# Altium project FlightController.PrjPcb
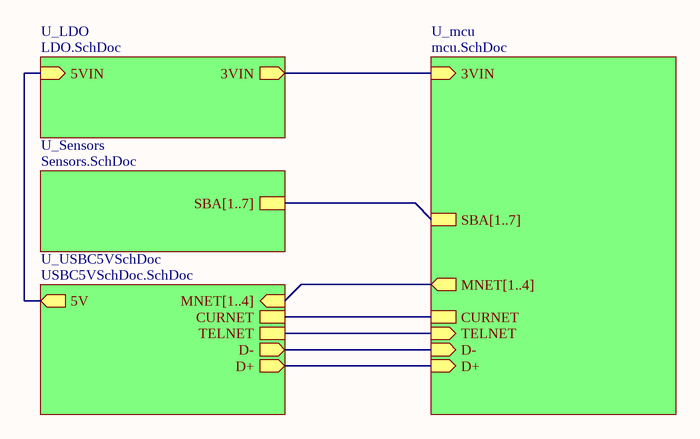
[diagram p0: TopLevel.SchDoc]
6 sheets, 64 parts. Net scope: hierarchical (ports join the sheet entries above them; power ports are global).
Board file: P2cbcopynext.PcbDoc
Sheets:
  TopLevel.SchDoc
    U_mcu = mcu.SchDoc
      U_VDDCap = VDDCap.SchDoc
      U_VDDCap = VDDCap.SchDoc
      U_VDDCap = VDDCap.SchDoc
      U_VDDCap = VDDCap.SchDoc
      U_VDDCap = VDDCap.SchDoc
    U_LDO = LDO.SchDoc
    U_Sensors = Sensors.SchDoc
      U_VDDCap = VDDCap.SchDoc
      U_VDDCap = VDDCap.SchDoc
      U_VDDCap = VDDCap.SchDoc
      U_VDDCap = VDDCap.SchDoc
    U_USBC5VSchDoc = USBC5VSchDoc.SchDoc

## Sheet TopLevel.SchDoc
size A; SheetNumber: 1; SheetTotal: 6

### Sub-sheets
U_LDO = LDO.SchDoc: 3VIN (out), 5VIN (in)
U_mcu = mcu.SchDoc: D- (in), D+ (in), TELNET (in), CURNET, 3VIN (in), SBA[1..7], MNET[1..4] (out)
U_Sensors = Sensors.SchDoc: SBA[1..7]
U_USBC5VSchDoc = USBC5VSchDoc.SchDoc: 5V (out), D+ (out), D- (out), MNET[1..4] (in), CURNET, TELNET

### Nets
3V3: sheet U_mcu/3VIN, sheet U_LDO/3VIN
5V_RAIL: sheet U_LDO/5VIN, sheet U_USBC5VSchDoc/5V
CURNET: sheet U_mcu/CURNET, sheet U_USBC5VSchDoc/CURNET
D+: sheet U_mcu/D+, sheet U_USBC5VSchDoc/D+
D-: sheet U_mcu/D-, sheet U_USBC5VSchDoc/D-
TELNET: sheet U_mcu/TELNET, sheet U_USBC5VSchDoc/TELNET

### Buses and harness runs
bus sheet U_mcu/MNET[1..4] = sheet U_USBC5VSchDoc/MNET[1..4]
bus sheet U_mcu/SBA[1..7] = sheet U_Sensors/SBA[1..7]

## Sheet mcu.SchDoc
size A; SheetNumber: 6; SheetTotal: 6
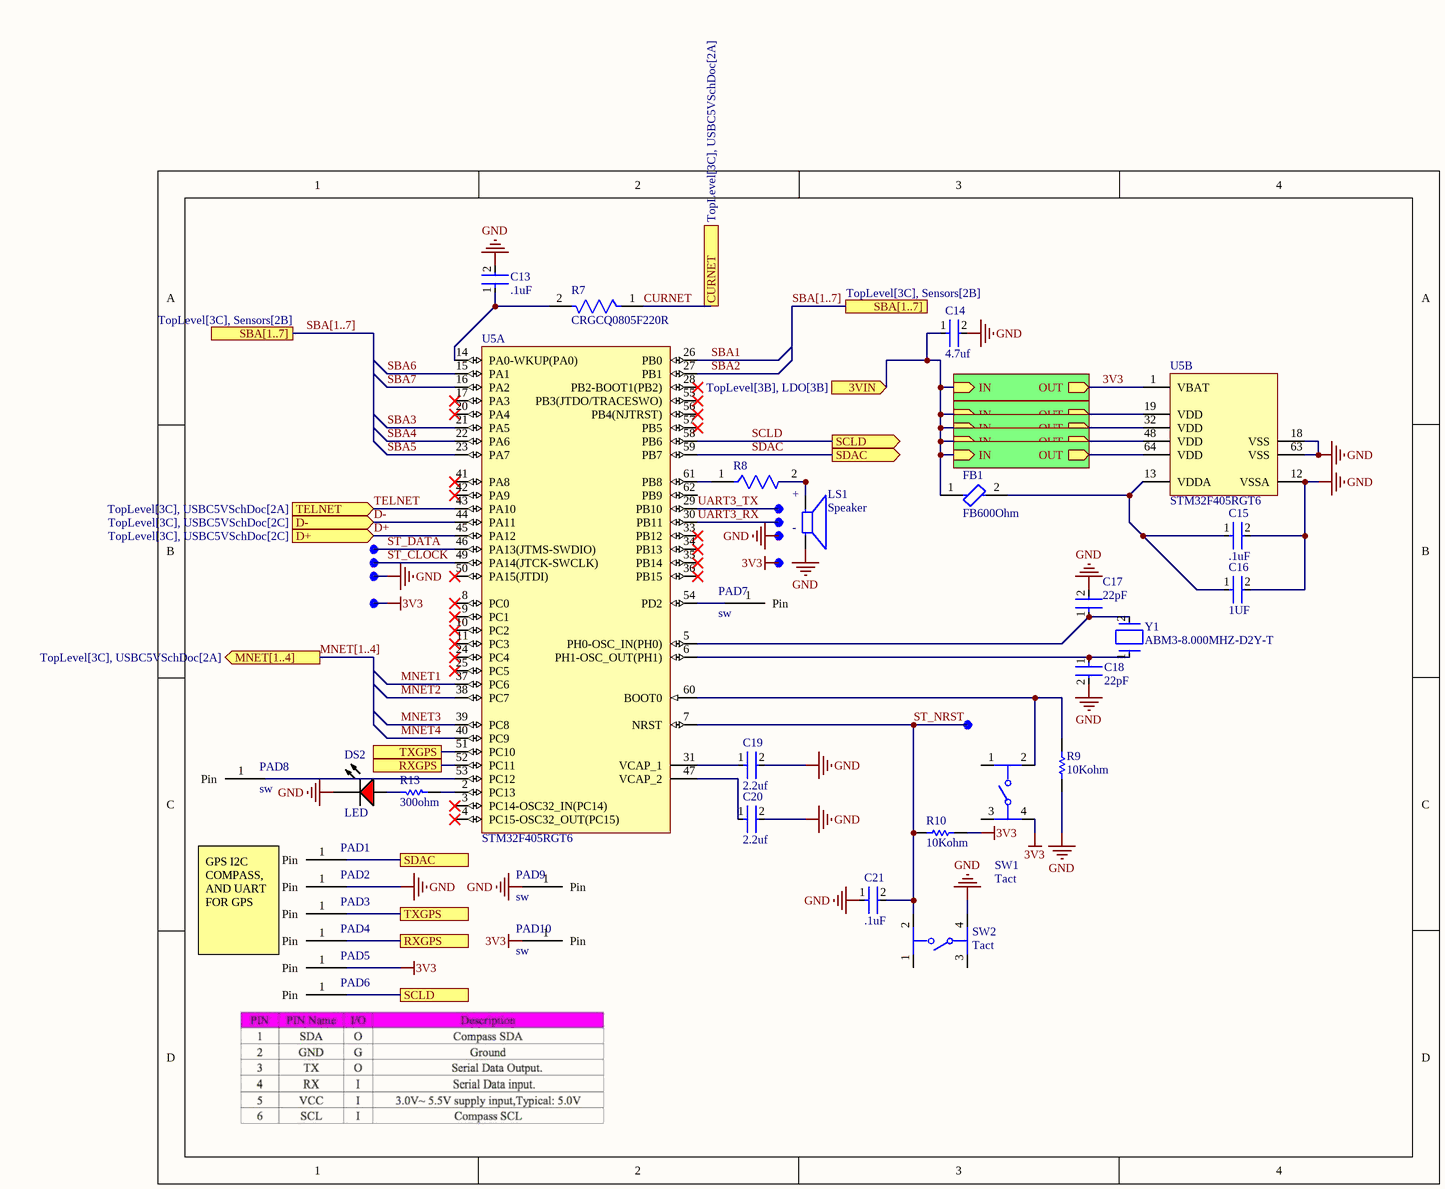
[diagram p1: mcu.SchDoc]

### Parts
C13  .1uF  [FP-C0603C-CF-MFG]
C14  4.7uf  [FP-CL10-IPC_C]
C15  .1uF  [FP-C0603C-CF-MFG]
C16  1UF  [FP-CC0805-0_85-MFG]
C17  22pF  [FP-C0805C-DN-MFG]
C18  22pF  [FP-C0805C-DN-MFG]
C19  2.2uf  [FP-CL10-IPC_A]
C20  2.2uf  [FP-CL10-IPC_A]
C21  .1uF  [FP-C0603C-CF-MFG]
DS2  LED  [LUMX-SML-LX1206IC_V]
FB1  FB600Ohm  [FP-BLM21-0_2-t0_85-e0_5-MFG]
LS1  Speaker  [XDCR_CMT-0525-75-SMT-TR]
PAD1  sw  [PCBComponent_1]  (value not drawn)
PAD2  sw  [PCBComponent_1]  (value not drawn)
PAD3  sw  [PCBComponent_1]  (value not drawn)
PAD4  sw  [PCBComponent_1]  (value not drawn)
PAD5  sw  [PCBComponent_1]  (value not drawn)
PAD6  sw  [PCBComponent_1]  (value not drawn)
PAD7  sw  [PCBComponent_1]
PAD8  sw  [PCBComponent_1]
PAD9  sw  [PCBComponent_1]
PAD10  sw  [PCBComponent_1]
R7  CRGCQ0805F220R  [FP-CRGCQ0805-IPC_C]
R8  100Ohm  [FP-RC0603-0_55-MFG]  (value not drawn)
R9  10Kohm  [RESC2013X60X35ML10T20]
R10  10Kohm  [RESC2013X60X35ML10T20]
R13  300ohm  [RESC1608X55X25LL10T15]
SW1  Tact  [FP-PTS647SM38SMTR2LFS-MFG]
SW2  Tact  [FP-PTS647SM38SMTR2LFS-MFG]
U5  STM32F405RGT6  [STM-LQFP64_M]  (parts A,B of 2)
Y1  ABM3-8.000MHZ-D2Y-T  [FP-ABM3-MFG]

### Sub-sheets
U_VDDCap = VDDCap.SchDoc: OUT (out), IN (in)
U_VDDCap = VDDCap.SchDoc: OUT (out), IN (in)
U_VDDCap = VDDCap.SchDoc: OUT (out), IN (in)
U_VDDCap = VDDCap.SchDoc: OUT (out), IN (in)
U_VDDCap = VDDCap.SchDoc: OUT (out), IN (in)

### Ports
3VIN (in, see TopLevel[3B], LDO[3B]), CURNET (see TopLevel[3C], USBC5VSchDoc[2A]), D+ (in, see TopLevel[3C], USBC5VSchDoc[2C]), D- (in, see TopLevel[3C], USBC5VSchDoc[2C]), MNET[1..4] (out, see TopLevel[3C], USBC5VSchDoc[2A]), RXGPS, SBA[1..7] (see TopLevel[3C], Sensors[2B]), SCLD, SCLD (out), SDAC, SDAC (out), TELNET (in, see TopLevel[3C], USBC5VSchDoc[2A]), TXGPS

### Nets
3V3: C14.1 FB1.1 PAD5.1(Pin) PAD10.1(Pin) R10.1 SW1.4 U5.1(VBAT) U5.19(VDD) U5.32(VDD) U5.48(VDD) U5.64(VDD) ; port 3VIN, sheet U_VDDCap/OUT, sheet U_VDDCap/IN, sheet U_VDDCap/OUT, sheet U_VDDCap/IN, sheet U_VDDCap/OUT, sheet U_VDDCap/IN, sheet U_VDDCap/OUT, sheet U_VDDCap/IN, sheet U_VDDCap/OUT, sheet U_VDDCap/IN
GND: C13.2 C14.2 C15.2 C16.2 C17.2 C18.2 C19.2 C20.2 C21.1 DS2.2(K) LS1.N PAD2.1(Pin) PAD9.1(Pin) R9.1 SW2.4 U5.12(VSSA) U5.18(VSS) U5.63(VSS)
CURNET: R7.1 ; port CURNET
D+: U5.45(PA12) ; port D+
D-: U5.44(PA11) ; port D-
MNET1: U5.37(PC6)
MNET2: U5.38(PC7)
MNET3: U5.39(PC8)
MNET4: U5.40(PC9)
SBA1: U5.26(PB0)
SBA2: U5.27(PB1)
SBA3: U5.21(PA5)
SBA4: U5.22(PA6)
SBA5: U5.23(PA7)
SBA6: U5.15(PA1)
SBA7: U5.16(PA2)
SCLD: PAD6.1(Pin) U5.58(PB6) ; port SCLD
SDAC: PAD1.1(Pin) U5.59(PB7) ; port SDAC
ST_CLOCK: U5.49(PA14(JTCK-SWCLK))
ST_DATA: U5.46(PA13(JTMS-SWDIO))
ST_NRST: C21.2 R10.2 SW2.2 U5.7(NRST)
TELNET: U5.43(PA10) ; port TELNET
UART3_RX: U5.30(PB11)
UART3_TX: U5.29(PB10)
NetC13_1: C13.1 R7.2 U5.14(PA0-WKUP(PA0))
NetC15_1: C15.1 C16.1 FB1.2 U5.13(VDDA)
NetC17_1: C17.1 U5.5(PH0-OSC_IN(PH0)) Y1.2
NetC18_1: C18.1 U5.6(PH1-OSC_OUT(PH1)) Y1.1
NetC19_1: C19.1 U5.31(VCAP_1)
NetC20_1: C20.1 U5.47(VCAP_2)
NetDS2_1: DS2.1(A) R13.1
NetLS1_P: LS1.P R8.2
NetPAD3_1: PAD3.1(Pin) U5.51(PC10) ; port TXGPS
NetPAD4_1: PAD4.1(Pin) U5.52(PC11) ; port RXGPS
NetPAD7_1: PAD7.1(Pin) U5.54(PD2)
NetPAD8_1: PAD8.1(Pin) U5.53(PC12)
NetR8_1: R8.1 U5.61(PB8)
NetR9_2: R9.2 SW1.2 U5.60(BOOT0)
NetR13_2: R13.2 U5.2(PC13)

Not connected (* = marked no-connect by the designer): SW1 1 3; SW2 1 3; U5 3(PC14-OSC32_IN(PC14))* 4(PC15-OSC32_OUT(PC15))* 8(PC0)* 9(PC1)* 10(PC2)* 11(PC3)* 17(PA3)* 20(PA4)* 24(PC4)* 25(PC5)* 28(PB2-BOOT1(PB2))* 33(PB12)* 34(PB13)* 35(PB14)* 36(PB15)* 41(PA8)* 42(PA9)* 50(PA15(JTDI))* 55(PB3(JTDO/TRACESWO))* 56(PB4(NJTRST))* 57(PB5)* 62(PB9)

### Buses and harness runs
bus MNET[1..4] = port MNET[1..4]
bus SBA[1..7] = port SBA[1..7]

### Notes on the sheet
- GPS I2C COMPASS, AND UART FOR GPS
- Labels drawn without touching a wire or pin: 3V3, GND

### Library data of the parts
C13 C15 C21 = CMP-2006-03061-2: CAP CER 0.1UF 50V X7R 0603; Manufacturer: KEMET; Manufacturer Part Number: C0603C104K5RACTU; Tolerance: 0.1; Temperature Coefficient: 30ppm/°C; Material: Ceramic; Automotive Grade: Grade 1; Value: 0.10 μF
C14 = CMP-13271-003017-1: Cap Ceramic 4.7uF 10V X5R ±10% Pad SMD 0603 +85°C T/R
C16 = CMP-2100-03605-2: CAP CER 1UF 25V X7R 0805; Manufacturer Part Number: CC0805KKX7R8BB105; Manufacturer: Yageo; Material: Ceramic; Tolerance: 0.1
C17 C18 = CMP-2007-00048-2: Capacitor; Ceramic; Cap; 22.0pF; Tol 5%; SMT; Vol-Rtg 50V; C0G; Tape and Reel; Manufacturer: KEMET; Manufacturer Part Number: C0805C220J5GACTU; Temperature Coefficient: 30ppm/°C; Tolerance: 0.05
C19 C20 = CMP-13271-003582-1: Cap Ceramic 2.2uF 10V X7R ±10% Pad SMD 0603 +125°C T/R
DS2 = CMP-2000-07123-1: LED Red, 65 mW, -40 to 85 degC, 2-Pin SMD, RoHS, Tape and Reel / SML-LX1206IC-TR; Manufacturer: Lumex; LED Material: GaAsP; Peak Wavelength: 635nm; Number of LEDs: 1; Viewing Angle: 160; Reverse Voltage: 5(Min)V; Lens Appearance: ColorlessNonDiffused; Intensity: 6mcd; Type: Uni-Color; Pin_Count: 2
FB1 = CMP-0686-00639-3: Chip Ferrite Bead, 0805, 600Ω @ 100MHz, 0.2Ω, 25%, 700mA; Material: Steel; DC Current: 200mA; Impedance: 600R; Current Rating: 600mA; Number of Circuits: 1; Shielding: Unshielded; DC Resistance (DCR): 210mR; Temperature Coefficient: 10ppm/°C; Conductor Material: Copper
LS1 = CMT-0525-75-SMT-TR: 5 mm, 3 Vo-p, 75 dB, Surface Mount (SMT), Magnetic Audio Transducer Buzzer / CMT-0525-75-SMT-TR; MF: Same Sky
PAD1-PAD10 = Comp
R7 = CMP-03211-009876-1: CRGCQ0805 220Ω 0.125W ±100ppm/°C 1% 150V; Manufacturer: TE Connectivity; Tolerance: 0.01; Automotive Grade: Grade 529
R8 = CMP-2100-03663-2: NexarPartId: 55402879; Voltage Rating: 50V; Power Rating: 100mW; Tolerance: 1%; Temperature Coefficient: 100ppm/°C; Resistance: 100Ω
R9 R10 = CMP-2000-05025-1: Chip Resistor, 10 KOhm, +/- 5%, 0.125 W, -55 to 155 degC, 0805 (2012 Metric), RoHS, Tape and Reel; Manufacturer: Yageo; Resistor Element Type: ThickFilm; Voltage Rating: 150V; Product Range: RCSeries; SVHC: ToBeAdvised; Resistor Case Style: 0805[2012Metric]; Temperature Coefficient: ±100ppm/degC; Power Rating: 250mW
R13 = CMP-2000-06958-1: Chip Resistor, 330 Ohm, +/- 5%, 50 V, -55 to 155 degC, 0603 (1608 Metric), -40 to 155 degC, RoHS, Tape and Reel / RC0603JR-07330RL; Manufacturer: Yageo; Temperature Coefficient: ±100ppm/°C; Power Rating: 100mW; Voltage Rating: 50V; Product Range: RCSeries; SVHC: ToBeAdvised; Resistance: 330ohm; Resistor Element Type: ThickFilm; Resistor Case Style: 0603[1608Metric]
SW1 SW2 = CMP-10040-000031-1: TACT 4.5 X 4.5, 3.8 MM H, 1.8N, / PTS647SM38SMTR2LFS; Operating Force: 180gf; Throw Configuration: SPST; Mechanical Life: 100000Cycles; Ratings: IP40; Switch Travel: 0.25mm; Switch Function: Off-Mom; Actuator Type: Standard; Illumination Type: Non-Illuminated
U5 = CMP-0243-00019-3: ARM Cortex-M4 32-bit MCU+FPU, 210 DMIPS, 1024 kB Flash, 192 kB Internal RAM, 51 I/Os, 64-pin LQFP, -40 to 85 degC, Tray; Manufacturer: STMicroelectronics; Supply Voltage(Vcc) min (V): 1.8; Supply Voltage(Vcc) max (V): 3.6; Internal RAM Size (kB): 192; I/Os (High Current): 51; D/A Converter: 2x12-bit; FLASH Size (Prog) (kB): 1024; Operating Frequency(F) (Processor speed) (MHz): 168
Y1 = CMP-2000-05033-2: Crystal 8MHz ±20ppm 18pF SMD-2 5mm x 3.2mm; Series Resistance: 500R; Frequency Stability: 30ppm; ESR (Equivalent Series Resistance): 140R

## Sheet VDDCap.SchDoc
size A; SheetNumber: 4; SheetTotal: 6
Used 9 times, as channels U_mcu/U_VDDCap, U_mcu/U_VDDCap, U_mcu/U_VDDCap, U_mcu/U_VDDCap, U_mcu/U_VDDCap, U_Sensors/U_VDDCap, U_Sensors/U_VDDCap, U_Sensors/U_VDDCap, U_Sensors/U_VDDCap. Parts and nets are listed once, with the designators drawn on the sheet.
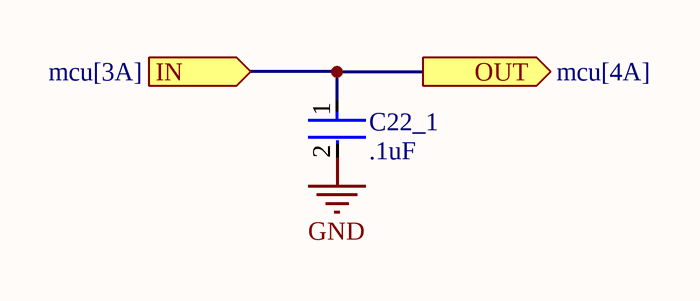
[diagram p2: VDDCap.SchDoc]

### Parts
C22_1  .1uF  [FP-C0603C-CF-MFG]

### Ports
IN (in, see mcu[3A]), OUT (out, see mcu[4A])

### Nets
GND: C22_1.2
IN: C22_1.1 ; port OUT, port IN

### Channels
U_mcu/U_VDDCap: designators end in _U_VDDCap5; ports IN=3V3 OUT=3V3
U_mcu/U_VDDCap: designators end in _U_VDDCap4; ports IN=3V3 OUT=3V3
U_mcu/U_VDDCap: designators end in _U_VDDCap3; ports IN=3V3 OUT=3V3
U_mcu/U_VDDCap: designators end in _U_VDDCap2; ports IN=3V3 OUT=3V3
U_mcu/U_VDDCap: designators end in _U_VDDCap1; ports IN=3V3 OUT=3V3
U_Sensors/U_VDDCap: designators end in _U_VDDCap9; ports IN=3V3 OUT=3V3
U_Sensors/U_VDDCap: designators end in _U_VDDCap8; ports IN=3V3 OUT=3V3
U_Sensors/U_VDDCap: designators end in _U_VDDCap7; ports IN=3V3 OUT=3V3
U_Sensors/U_VDDCap: designators end in _U_VDDCap6; ports IN=3V3 OUT=3V3

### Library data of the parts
C22_1 = CMP-2006-03061-2: as C13 on sheet mcu

## Sheet LDO.SchDoc
size A; SheetNumber: 5; SheetTotal: 6
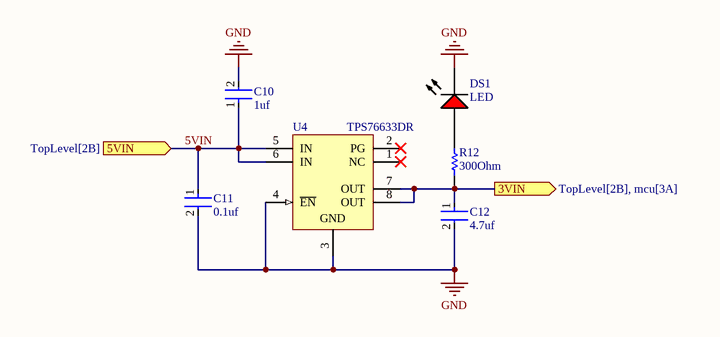
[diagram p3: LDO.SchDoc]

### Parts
C10  1uf  [FP-CC0805-0_85-MFG]
C11  0.1uf  [FP-CC0805-0_85-MFG]
C12  4.7uf  [FP-CL10-IPC_C]
DS1  LED  [LUMX-SML-LX1206IC_V]
R12  300Ohm  [RESC1608X55X25LL10T15]
U4  TPS76633DR  [D0008A_N]

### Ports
3VIN (out, see TopLevel[2B], mcu[3A]), 5VIN (in, see TopLevel[2B])

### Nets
3V3: C12.1 R12.1 U4.7(OUT) U4.8(OUT) ; port 3VIN
GND: C10.2 C11.2 C12.2 DS1.2(K) U4.3(GND) U4.4(~{EN})
5VIN: C10.1 C11.1 U4.5(IN) U4.6(IN) ; port 5VIN  [project net 5V_RAIL]
NetDS1_1: DS1.1(A) R12.2

Not connected (* = marked no-connect by the designer): U4 1(NC)* 2(PG)*

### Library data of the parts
C10 = CMP-2100-03605-2: as C16 on sheet mcu
C11 = CMP-2007-01272-2: CC0805 100 nF X7R 10.00% 50 V; Manufacturer: Yageo; Manufacturer Part Number: CC0805KPX7R9BB104; Tolerance: 0.1; Material: Ceramic; Voltage Rating: 50 V; Value: 100 nF
C12 = CMP-13271-003017-1: as C14 on sheet mcu
DS1 = CMP-2000-07123-1: as DS2 on sheet mcu
R12 = CMP-2000-06958-1: as R13 on sheet mcu
U4 = CMP-0394-00013-2: Single Output LDO, 250 mA, Fixed 3.3 V Output, 2.7 to 10 V Input, with Low IQ, 8-pin SOIC (D), -40 to 125 degC, Green (RoHS & no Sb/Br); Manufacturer: Texas Instruments; Power Good: TRUE; Vdo(Typ)(mV): 230; Fixed Output Options(V): 3.3; Iout(Max)(A): 0.25; Iq(Typ)(mA): 0.03; Vin(Max)(V): 10; SubFamily: Single Channel LDO; Vin(Min)(V): 2.7

## Sheet Sensors.SchDoc
size 381 x 241 mm; SheetNumber: 3; SheetTotal: 6
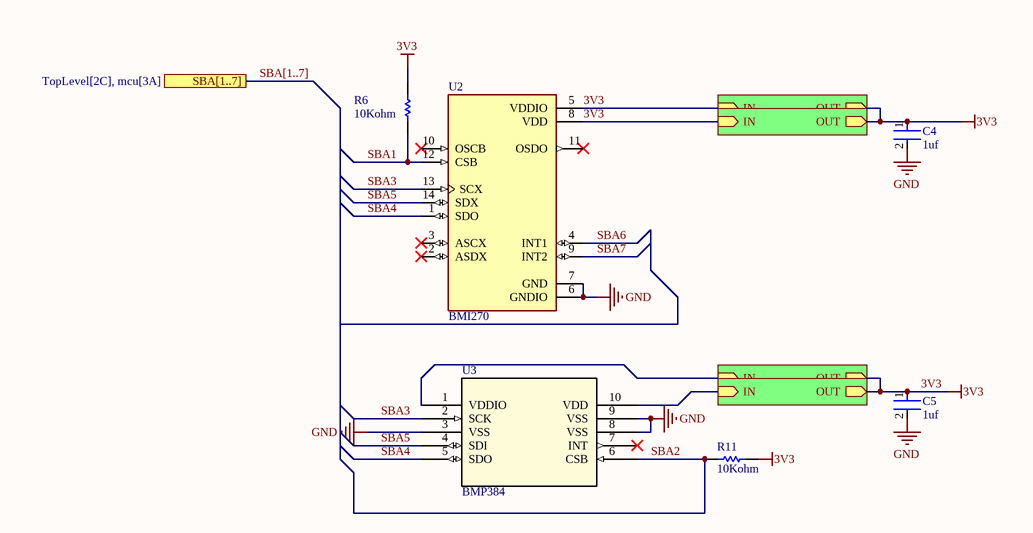
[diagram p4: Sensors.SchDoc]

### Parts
C4  1uf  [FP-CC0805-0_85-MFG]
C5  1uf  [FP-CC0805-0_85-MFG]
R6  10Kohm  [RESC2013X60X35ML10T20]
R11  10Kohm  [RESC2013X60X35ML10T20]
U2  BMI270  [XDCR_BMI270]
U3  BMP384  [LGA10_2.0X2.0X0.95_BOS]

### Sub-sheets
U_VDDCap = VDDCap.SchDoc: OUT (out), IN (in)
U_VDDCap = VDDCap.SchDoc: OUT (out), IN (in)
U_VDDCap = VDDCap.SchDoc: OUT (out), IN (in)
U_VDDCap = VDDCap.SchDoc: OUT (out), IN (in)

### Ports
SBA[1..7] (see TopLevel[2C], mcu[3A])

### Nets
3V3: C4.1 C5.1 R6.1 R11.1 U2.5(VDDIO) U2.8(VDD) U3.1(VDDIO) U3.10(VDD) ; sheet U_VDDCap/OUT, sheet U_VDDCap/IN, sheet U_VDDCap/OUT, sheet U_VDDCap/IN, sheet U_VDDCap/OUT, sheet U_VDDCap/IN, sheet U_VDDCap/OUT, sheet U_VDDCap/IN
GND: C4.2 C5.2 U2.6(GNDIO) U2.7(GND) U3.3(VSS) U3.8(VSS) U3.9(VSS)
SBA1: R6.2 U2.12(CSB)
SBA2: R11.2 U3.6(CSB)
SBA3: U2.13(SCX) U3.2(SCK)
SBA4: U2.1(SDO) U3.5(SDO)
SBA5: U2.14(SDX) U3.4(SDI)
SBA6: U2.4(INT1)
SBA7: U2.9(INT2)

Not connected (* = marked no-connect by the designer): U2 2(ASDX)* 3(ASCX)* 10(OSCB)* 11(OSDO)*; U3 7(INT)*

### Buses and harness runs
bus SBA[1..7] = port SBA[1..7]

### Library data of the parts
C4 C5 = CMP-2100-03605-2: as C16 on sheet mcu
R6 R11 = CMP-2000-05025-1: as R9 on sheet mcu
U2 = BMI270: Accelerometer, Gyroscope, 6 Axis Sensor IÂ²C, SPI Output; MF: Bosch Sensortec
U3 = BMP384: Description; Manufacturer_Name: Bosch Sensortec

## Sheet USBC5VSchDoc.SchDoc
size A; SheetNumber: 2; SheetTotal: 6
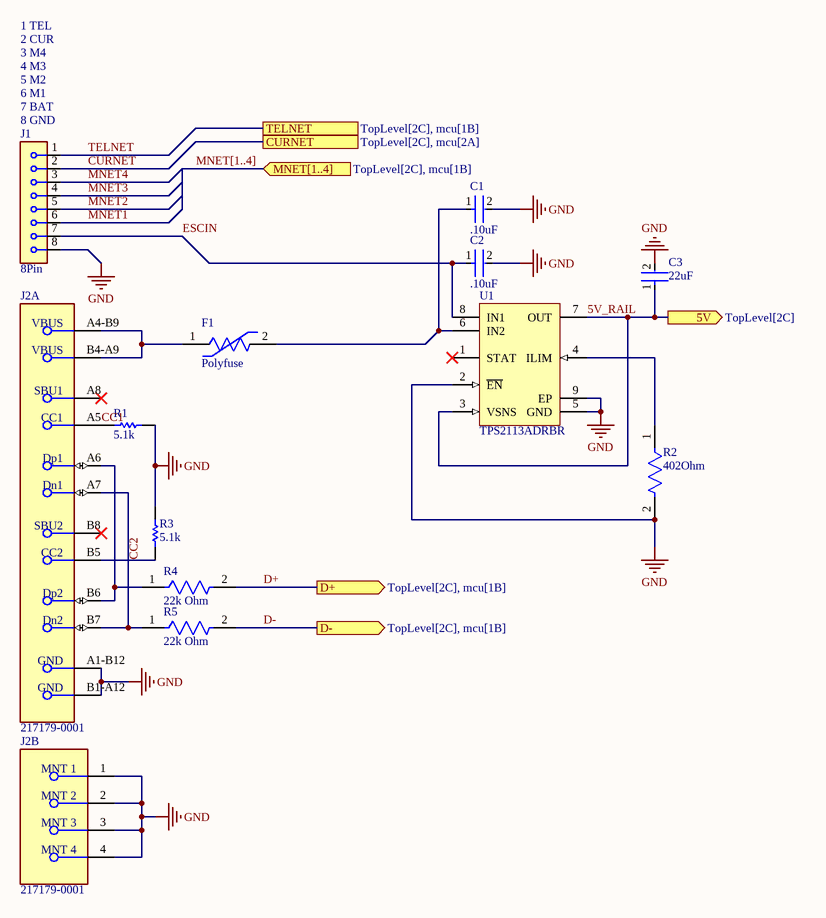
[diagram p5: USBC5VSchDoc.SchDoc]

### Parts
C1  .10uF  [FP-C0805C-DN-MFG]
C2  .10uF  [FP-C0805C-DN-MFG]
C3  22uF  [FP-CL21-IPC_A]
F1  Polyfuse  [FP-1206L-MFG]
J1  8Pin  [JST_SM08B-SRSS-TB]
J2  217179-0001  [FP-2171790001-MFG]  (parts A,B of 2)
R1  5.1k  [RESC2013X60X35ML10T20]
R2  402Ohm  [FP-CRCW0805-e3-IPC_A]
R3  5.1k  [RESC2013X60X35ML10T20]
R4  22k Ohm  [FP-CRCW0805-e3-IPC_C]
R5  22k Ohm  [FP-CRCW0805-e3-IPC_C]
U1  TPS2113ADRBR  [DRB0008B_V]

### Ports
5V (out, see TopLevel[2C]), CURNET (see TopLevel[2C], mcu[2A]), D+ (out, see TopLevel[2C], mcu[1B]), D- (out, see TopLevel[2C], mcu[1B]), MNET[1..4] (in, see TopLevel[2C], mcu[1B]), TELNET (see TopLevel[2C], mcu[1B])

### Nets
GND: C1.2 C2.2 C3.2 J1.8 J2.1(MNT_1) J2.2(MNT_2) J2.3(MNT_3) J2.4(MNT_4) J2.A1-B12(GND) J2.B1-A12(GND) R1.2 R2.2 R3.2 U1.2(~{EN}) U1.5(GND) U1.9(EP)
5V_RAIL: C3.1 U1.3(VSNS) U1.7(OUT) ; port 5V
CC1: J2.A5(CC1) R1.1
CC2: J2.B5(CC2) R3.1
CURNET: J1.2 ; port CURNET
D+: R4.2 ; port D+
D-: R5.2 ; port D-
ESCIN: C2.1 J1.7 U1.8(IN1)
MNET1: J1.6
MNET2: J1.5
MNET3: J1.4
MNET4: J1.3
TELNET: J1.1 ; port TELNET
NetC1_1: C1.1 F1.2 U1.6(IN2)
NetF1_1: F1.1 J2.A4-B9(VBUS) J2.B4-A9(VBUS)
NetJ2_A6: J2.A6(Dp1) J2.B6(Dp2) R4.1
NetJ2_A7: J2.A7(Dn1) J2.B7(Dn2) R5.1
NetR2_1: R2.1 U1.4(ILIM)

Not connected (* = marked no-connect by the designer): J2 A8(SBU1)* B8(SBU2)*; U1 1(STAT)*

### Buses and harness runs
bus MNET[1..4] = port MNET[1..4]

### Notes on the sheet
- 1 TEL
- 2 CUR
- 3 M4
- 4 M3
- 5 M2
- 6 M1
- (near J1) 7 BAT
- (near J1) 8 GND

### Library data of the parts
C1 C2 = CMP-2007-00279-2: CAP CER 0.1UF 50V X7R 0805; Manufacturer Part Number: C0805C104K5RACTU; Manufacturer: KEMET; Value: 0.10 μF; Tolerance: 0.1; Temperature Coefficient: 30ppm/°C; Material: Ceramic
C3 = CMP-13271-000185-1: CL21 Series 0805 22uF 6.3V ±20% Tolerance X5R Multilayer Ceramic Chip Capacitor
F1 = CMP-08606-000042-1: PTC RESET FUSE 8V 1.1A 1206; Manufacturer Part Number: 1206L110THYR; Manufacturer: Littelfuse; Trip Time: 0.1s; Trip Current: 2.2A; Value: 0.04-0.21Ω; Current Rating: 100A
J1 = SM08B-SRSS-TB: SH Series 8 Position 1 mm Pitch Surface Mount Side Entry Shrouded Header / SM08B-SRSS-TB; MF: {'manufacturer': u'JST Sales America Inc.'}
J2 = CMP-04767-000028-2: CONN RCP USB2.0 TYP C 24P SMD RA; NexarPartId: 117190526; Gender: Receptacle; Number of Contacts: 16; Current Rating: 1.25A; Voltage Rating: 30V
R1 R3 = CMP-2001-01390-1: Part Number: RC0805JR-075K1L; Manufacturer: Yageo
R2 = CMP-2001-03902-2: RES Thick Film, 402Ω, 1%, 0.125W, 100ppm/°C, 0805; Voltage Rating: 150V; Max Power Dissipation: 125mW; Resistance: 402R
R4 R5 = CMP-2001-03692-2: RES Thick Film, 22Ω, 1%, 0.125W, 100ppm/°C, 0805; Resistance: 22R; Power Rating: 125mW; Voltage Rating: 150V
U1 = CMP-0339-00015-2: Dual In / Single Out Autoswitching Power Mux, 2.8 to 5.5 V, -40 to 85 degC, 9-pin SON (DRB), Green (RoHS & no Sb/Br); Manufacturer: Texas Instruments; IN1, IN2 Input Voltage(Min)(V): 2.8; SubFamily: Power Multiplexer (MUX); IN1 rDS(on)(Typ)(mOhm): 84; IN2 rDS(on)(Typ)(Ohms): 0.084; Number of Inputs: 2; IN1, IN2 Input Voltage(Max)(V): 5.5; IN2 Output Current(Max)(A): 1.25

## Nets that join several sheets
3V3: mcu (11 pins), U_mcu/U_VDDCap (C22_1_U_VDDCap5.1), U_mcu/U_VDDCap (C22_1_U_VDDCap4.1), U_mcu/U_VDDCap (C22_1_U_VDDCap3.1), U_mcu/U_VDDCap (C22_1_U_VDDCap2.1), U_mcu/U_VDDCap (C22_1_U_VDDCap1.1), LDO (C12.1 R12.1 U4.7 U4.8), Sensors (8 pins), U_Sensors/U_VDDCap (C22_1_U_VDDCap9.1), U_Sensors/U_VDDCap (C22_1_U_VDDCap8.1), U_Sensors/U_VDDCap (C22_1_U_VDDCap7.1), U_Sensors/U_VDDCap (C22_1_U_VDDCap6.1)
GND: mcu (18 pins), U_mcu/U_VDDCap (C22_1_U_VDDCap5.2), U_mcu/U_VDDCap (C22_1_U_VDDCap4.2), U_mcu/U_VDDCap (C22_1_U_VDDCap3.2), U_mcu/U_VDDCap (C22_1_U_VDDCap2.2), U_mcu/U_VDDCap (C22_1_U_VDDCap1.2), LDO (6 pins), Sensors (7 pins), U_Sensors/U_VDDCap (C22_1_U_VDDCap9.2), U_Sensors/U_VDDCap (C22_1_U_VDDCap8.2), U_Sensors/U_VDDCap (C22_1_U_VDDCap7.2), U_Sensors/U_VDDCap (C22_1_U_VDDCap6.2), USBC5VSchDoc (16 pins)
5V_RAIL: LDO (C10.1 C11.1 U4.5 U4.6), USBC5VSchDoc (C3.1 U1.3 U1.7)
CURNET: mcu (R7.1), USBC5VSchDoc (J1.2)
D+: mcu (U5.45), USBC5VSchDoc (R4.2)
D-: mcu (U5.44), USBC5VSchDoc (R5.2)
MNET1: mcu (U5.37), USBC5VSchDoc (J1.6)
MNET2: mcu (U5.38), USBC5VSchDoc (J1.5)
MNET3: mcu (U5.39), USBC5VSchDoc (J1.4)
MNET4: mcu (U5.40), USBC5VSchDoc (J1.3)
SBA1: mcu (U5.26), Sensors (R6.2 U2.12)
SBA2: mcu (U5.27), Sensors (R11.2 U3.6)
SBA3: mcu (U5.21), Sensors (U2.13 U3.2)
SBA4: mcu (U5.22), Sensors (U2.1 U3.5)
SBA5: mcu (U5.23), Sensors (U2.14 U3.4)
SBA6: mcu (U5.15), Sensors (U2.4)
SBA7: mcu (U5.16), Sensors (U2.9)
TELNET: mcu (U5.43), USBC5VSchDoc (J1.1)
